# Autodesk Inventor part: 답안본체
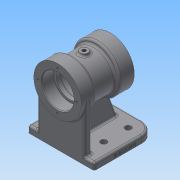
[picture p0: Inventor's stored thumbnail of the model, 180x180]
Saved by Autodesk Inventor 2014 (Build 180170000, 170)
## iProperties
Created: 2020-06
Part Number: 답안본체
Material: 일반
Document SubType Name: Modeling
Designer: net
Density: 1 g/cm^3
Appearance: 기본값
Author: net
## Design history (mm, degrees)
sketch "스케치1"
  geometry: L1 (0, 0)-(78, 0); L2 (0, 0)-(0, 35); L3 (0, 35)-(22, 35); L4 (22, 35)-(22, 29); L5 (22, 29)-(56, 29); L6 (56, 29)-(56, 35); L7 (56, 35)-(78, 35); L8 (78, 35)-(78, 0)
  constraints: 16 end point, 4 parallel, 2 perpendicular, 1 collinear, 1 horizontal
  dimensions: "d0" = 78 distance of L1.start L1.end; "d1" = 70 diameter of L2.end L1; "d2" = 22 distance of L2.end L3.end; "d3" = 22 distance of L6.end L7.end; "d4" = 58 diameter of L5 L1; "d5" = 70 diameter of L7 L1
revolve "회전1" sketch "스케치1" stored, may be unused: angle "d6" = 90 deg
fillet "모깎기1" dims "d7" = 3
sketch "스케치2"
  geometry: L1 (25, 29)-(53, 29) reference; L2 (59, 35)-(78, 35) reference; L3 (78, 35)-(78, -35) reference; L4 (78, -35)-(59, -35) reference; L5 (53, -29)-(25, -29) reference; L6 (19, -35)-(0, -35) reference; L7 (0, -35)-(0, 35) reference; L8 (0, 35)-(19, 35) reference; L9 (0, 0)-(78, 0); L10 (0, 0)-(0, 23.5); L11 (0, 23.5)-(17.7, 23.5); L12 (18, 23.2)-(18, 20); L13 (18, 20)-(24, 20); L14 (24, 20)-(24, 20); L15 (27, 23)-(51, 23); L16 (54, 20)-(54, 20); L17 (54, 20)-(60, 20); L18 (60, 20)-(60, 23.2); L19 (60.3, 23.5)-(78, 23.5); L20 (78, 0)-(78, 23.5); A1 r 3 centre (19, 32) between (22, 32) and (19, 35) reference; A2 r 3 centre (25, 32) between (22, 32) and (25, 29) reference; A3 r 3 centre (53, 32) between (53, 29) and (56, 32) reference; A4 r 3 centre (59, 32) between (59, 35) and (56, 32) reference; A5 r 3 centre (59, -32) between (56, -32) and (59, -35) reference; A6 r 3 centre (53, -32) between (56, -32) and (53, -29) reference; A7 r 3 centre (25, -32) between (25, -29) and (22, -32) reference; A8 r 3 centre (19, -32) between (19, -35) and (22, -32) reference; A9 r 0.3 centre (17.7, 23.2) between (18, 23.2) and (17.7, 23.5); A10 r 0.3 centre (60.3, 23.2) between (60.3, 23.5) and (60, 23.2); A11 r 3 centre (27, 20) between (27, 23) and (24, 20); A12 r 3 centre (51, 20) between (54, 20) and (51, 23); 2 further points
  constraints: 24 end point, 8 point on circle, 8 tangent, 6 parallel, 6 point on line, 4 centre point, 4 perpendicular, 2 equal radius, 1 midpoint
  dimensions: "d8" = 47 diameter of L10.end L9; "d9" = 47 diameter of L19.end L9; "d10" = 40 diameter of L12.end L9; "d12" = 40 diameter of L17.end L9; "d13" = 46 diameter of L15 L9; "d14" = 18 distance of L10.end point (18, 23.5); "d15" = 6 distance of L12.end L13.end; "d16" = 18 distance of point (60, 23.5) L19.end; "d17" = 6 distance of L16.end L17.end; "d18" = 0.3 radius of A9; "d19" = 3 radius of A11
revolve "회전2" sketch "스케치2" stored, may be unused: angle "d20" = 90 deg
chamfer "모따기1" distance "d21" = 1; stored, may be unused: second distance "d22" = 2, angle "d23" = 45 deg
node "작업 평면1"
sketch "스케치3"
  geometry: L1 (49, 5)-(-49, 5); L2 (-49, 5)-(-49, 75); L3 (-29, 95)-(29, 95); L4 (49, 75)-(49, 5); L5 (49, 5)-(-49, 95); L6 (-49, 5)-(49, 95); A1 r 20 centre (-29, 75) between (-29, 95) and (-49, 75); A2 r 20 centre (29, 75) between (49, 75) and (29, 95); 3 further points
  constraints: 12 end point, 4 point on circle, 4 point on line, 4 tangent, 3 midpoint, 2 centre point, 2 parallel, 1 equal radius, 1 horizontal, 1 perpendicular, 1 vertical alignment
  dimensions: "d25" = 5 distance from line of L1 point (0, 0); "d26" = 90 distance of L1.end L5.end; "d27" = 98 distance of L5.end L6.end; "d28" = 20 radius of A1
extrude "돌출1" join sketch "스케치3" distance "d29" = 10; taper "d30" = 0 deg
fillet "모깎기2" dims "d31" = 3
node "작업 평면2"
sketch "스케치6"
  geometry: L1 (0, 10)-(92, 10) reference; L2 (46, 10)-(81, 10); L3 (81, 10)-(81, 80); L4 (46, 10)-(11, 10); L5 (11, 10)-(11, 80); L6 (92, 0)-(92, 10) reference; L7 (0, 10)-(92, 10) reference; L8 (0, 0)-(0, 10) reference; L9 (92, 0)-(0, 0) reference; C1 r 23.5 at (46, 80) reference; C2 r 35 at (46, 80) reference; 1 further point
  constraints: 8 end point, 2 perpendicular, 2 point on line, 1 midpoint
  dimensions: "d49" = 35 distance of L2.start L2.end; "d50" = 35 distance of L2.start L4.end
feature "리브3" sketch "스케치6" dims "d51" = 1, "d52" = 10, "d53" = 0, "d54" = 0, "d55" = 1, "d56" = 1
node "작업 평면3"
sketch "스케치7"
  geometry: L1 (-35, -56)-(-35, -60) reference; L2 (-35, -60)-(0, -60) reference; L3 (0, -60)-(0, 20) reference; L4 (0, 20)-(10, 20) reference; L5 (10, 20)-(10, -70) reference; L6 (10, -70)-(-35, -70) reference; L7 (-35, -70)-(-35, -75) reference; L8 (-35, -75)-(-45.5, -75) reference; L9 (-45.5, -75)-(-46.5, -74) reference; L10 (-46.5, -74)-(-46.5, -57.3) reference; L11 (-46.8, -57)-(-50, -57) reference; L12 (-50, -57)-(-50, -51) reference; L13 (-47, -48)-(-47, -24) reference; L14 (-50, -21)-(-50, -15) reference; L15 (-50, -15)-(-46.8, -15) reference; L16 (-46.5, -14.7)-(-46.5, 2) reference; L17 (-46.5, 2)-(-45.5, 3) reference; L18 (-45.5, 3)-(-35, 3) reference; L19 (-35, 3)-(-35, -16) reference; L20 (-41, -22)-(-41, -50) reference; L21 (-99, -50)-(-99, -22) reference; L22 (-105, -16)-(-105, 3) reference; L23 (-105, 3)-(-94.5, 3) reference; L24 (-94.5, 3)-(-93.5, 2) reference; L25 (-93.5, 2)-(-93.5, -14.7) reference; L26 (-93.2, -15)-(-90, -15) reference; L27 (-90, -15)-(-90, -21) reference; L28 (-93, -24)-(-93, -48) reference; L29 (-90, -51)-(-90, -57) reference; L30 (-90, -57)-(-93.2, -57) reference; L31 (-93.5, -57.3)-(-93.5, -74) reference; L32 (-93.5, -74)-(-94.5, -75) reference; L33 (-94.5, -75)-(-105, -75) reference; L34 (-105, -75)-(-105, -56) reference; L35 (0, 8)-(-44.985, -8.373); L36 (0, 8)-(0, -60); A1 r 3 centre (-38, -56) between (-35, -56) and (-38, -53) reference; A2 r 0.3 centre (-46.8, -57.3) between (-46.5, -57.3) and (-46.8, -57) reference; A3 r 3 centre (-50, -48) between (-50, -51) and (-47, -48) reference; A4 r 3 centre (-50, -24) between (-47, -24) and (-50, -21) reference; A5 r 0.3 centre (-46.8, -14.7) between (-46.8, -15) and (-46.5, -14.7) reference; A6 r 3 centre (-38, -16) between (-38, -19) and (-35, -16) reference; A7 r 3 centre (-38, -22) between (-38, -19) and (-41, -22) reference; A8 r 3 centre (-38, -50) between (-41, -50) and (-38, -53) reference; A9 r 3 centre (-102, -56) between (-102, -53) and (-105, -56) reference; A10 r 3 centre (-102, -50) between (-102, -53) and (-99, -50) reference; A11 r 3 centre (-102, -22) between (-99, -22) and (-102, -19) reference; A12 r 3 centre (-102, -16) between (-105, -16) and (-102, -19) reference; A13 r 0.3 centre (-93.2, -14.7) between (-93.5, -14.7) and (-93.2, -15) reference; A14 r 3 centre (-90, -24) between (-90, -21) and (-93, -24) reference; A15 r 3 centre (-90, -48) between (-93, -48) and (-90, -51) reference; A16 r 0.3 centre (-93.2, -57.3) between (-93.2, -57) and (-93.5, -57.3) reference; 1 further point
  constraints: 4 end point, 1 collinear, 1 point on line
  dimensions: "d57" = 12 vertical distance of L4.end L35.start; "d58" = 70 deg angle of L3 L35
feature "리브4" sketch "스케치7" dims "d59" = 1, "d60" = 10, "d61" = 0, "d62" = 0, "d63" = 1, "d64" = 1
fillet "모깎기4" dims "d65" = 3
fillet "모깎기5" dims "d66" = 3
fillet "모깎기6" dims "d67" = 3
fillet "모깎기7" dims "d68" = 3
sketch "스케치8"
  geometry: L1 (46, 5)-(-46, 5) reference; C1 r 4.5 at (-29, 75); 1 further point
  constraints: 1 centre point
  dimensions: "d69" = 9 diameter of C1; "d70" = 29 horizontal distance of point (0, 0) C1.centre; "d71" = 70 distance from line of C1.centre L1
extrude "돌출2" cut sketch "스케치8" stored distance "d72" = 10; taper "d73" = 0 deg
sketch "스케치9"
  geometry: C1 r 35 at (0, 0) reference; 1 further point
  constraints: 1 vertical alignment
  dimensions: "d80" = 28.5 distance of C1.centre point (0, 28.5)
hole "구멍1" sketch "스케치9" at (0, 28.5) diameter "d81" = 3.242; stored, may be unused: countersink angle "d85" = 90 deg, drill point angle "d87" = 118 deg; dims "d82" = 10, "d83" = 4, "d84" = 2, "d86" = 12
node "작업 평면4"
node "작업 평면5"
sketch "스케치10"
  geometry: L1 (1.621, 0)-(-1.621, 0) reference; C1 r 6 at (0, 39); 1 further point
  constraints: 1 centre point, 1 vertical alignment
  dimensions: "d92" = 12 diameter of C1; "d93" = 39 distance from line of C1.centre L1
extrude "돌출3" join sketch "스케치10" stored distance "d94" = 3; taper "d95" = 0 deg
sketch "스케치11"
  geometry: C1 r 6 at (0, 0) reference; 2 further points
  constraints: 1 coincident
hole "구멍2" sketch "스케치11" at (0, 0) diameter "d96" = 5.188; stored, may be unused: countersink angle "d100" = 90 deg, drill point angle "d102" = 118 deg; dims "d97" = 10, "d98" = 4, "d99" = 2, "d101" = 12
fillet "모깎기8" dims "d103" = 3
sketch "스케치12"
  geometry: L1 (0, 67)-(0, 0) reference; L2 (-7, -3)-(0, -3) reference; 2 further points
  constraints: 1 other
  dimensions: "d104" = 4 distance from line of L1 point (-4, 42); "d105" = 45 distance from line of point (-4, 42) L2
feature "엠보싱1" sketch "스케치12" dims "d0" = 78, "d1" = 70, "d2" = 22, "d3" = 22, "d4" = 58, "d5" = 70, "d106" = 0.5, "d107" = 0
node "솔리드1"
pattern_linear "직사각형 패턴1" dims "d76" = 36, "d79" = 58
pattern_circular "원형 패턴1" dims angle "d89" = 360 deg
mirror "대칭1"
node "절단 모서리 투영1"
node "절단 모서리 투영4"
node "절단 모서리 투영5"
other parameters: "d91" = 32
